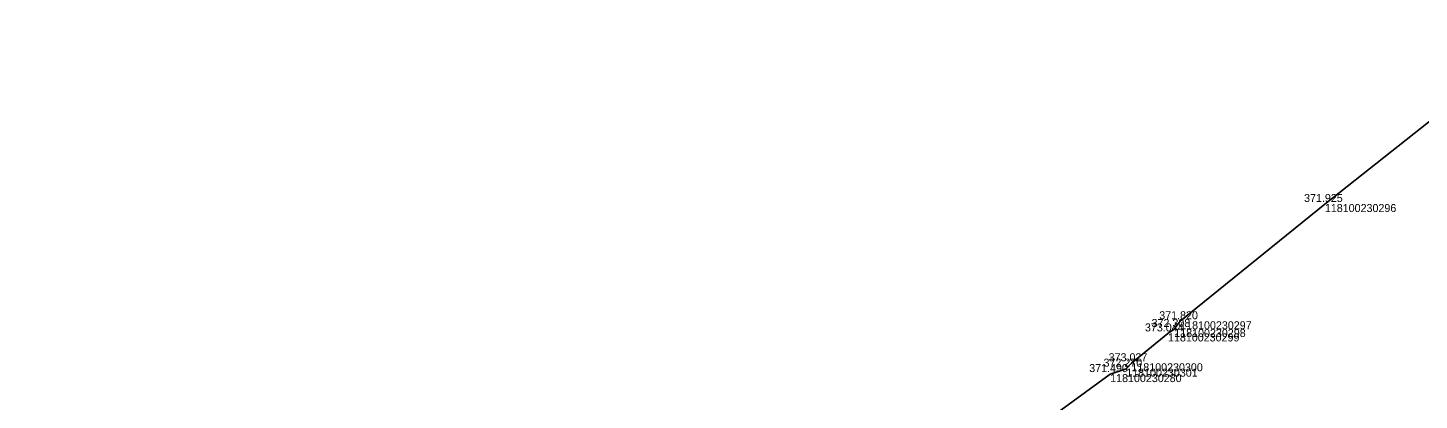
# Model space of a CAD drawing. Extents: x -732194 to -724760, y -944826 to -941477.
# Drawn here: x -731285.3 to -731076.7, y -942063.9 to -942008.1 of the extents above; entities that cross this region are included whole.
import ezdxf

# ---------------------------------------------------------------- set-up
doc = ezdxf.new("R2010")
doc.units = 0
for name, color, linetype in [('Vrstva 28', 7, 'Continuous'), ('Vrstva 31', 7, 'Continuous'), ('Vrstva 60', 7, 'Continuous'), ('Vrstva 61', 7, 'Continuous')]:
    doc.layers.add(name, color=color, linetype=linetype)

msp = doc.modelspace()

# ---------------------------------------------------------------- linework, layer by layer
at = {"layer": 'Vrstva 28'}
for points in [[(-731120.63, -942059.14), (-731119.86, -942058.33), (-731114.37, -942053.86), (-731113.43, -942053.2), (-731112.54, -942052.04), (-731090.85, -942034.48), (-731069.83, -942017.9), (-731057.45, -942008.09), (-731057.75, -942008.68)], [(-731285.31, -942325.58), (-731274.63, -942296.13), (-731267.63, -942279.07), (-731266.95, -942274.49), (-731266.31, -942268.77), (-731264.93, -942263.18), (-731264.13, -942256.92), (-731261.56, -942253.47), (-731256.01, -942237.5), (-731249.14, -942218.64), (-731239.5, -942196.85), (-731231.6, -942185.67), (-731225.39, -942175.28), (-731213.45, -942158.32), (-731200.78, -942140.85), (-731190.41, -942127.04), (-731184.79, -942121.18), (-731179.39, -942115.86), (-731166.81, -942100.28), (-731147.61, -942080.55), (-731141.71, -942075.09), (-731134.15, -942068.06), (-731123.04, -942059.95), (-731120.63, -942059.14)]]:
    msp.add_lwpolyline(points, dxfattribs=at)
at = {"layer": 'Vrstva 31'}
for points in [[(-731057.45, -942008.09), (-731069.83, -942017.9), (-731090.85, -942034.48), (-731112.54, -942052.04), (-731113.43, -942053.2), (-731114.37, -942053.86), (-731119.86, -942058.33), (-731120.63, -942059.14)], [(-731120.63, -942059.14), (-731123.04, -942059.95), (-731134.15, -942068.06)]]:
    msp.add_lwpolyline(points, dxfattribs=at)
at = {"layer": 'Vrstva 60'}
for p, q in [((-731090.85, -942034.48), (-731090.85, -942034.48)), ((-731113.43, -942053.2), (-731113.43, -942053.2)), ((-731112.54, -942052.04), (-731112.54, -942052.04)), ((-731114.37, -942053.86), (-731114.37, -942053.86)), ((-731123.04, -942059.95), (-731123.04, -942059.95)), ((-731120.63, -942059.14), (-731120.63, -942059.14)), ((-731119.86, -942058.33), (-731119.86, -942058.33))]:
    msp.add_line(p, q, dxfattribs=at)

# ---------------------------------------------------------------- texts
for s, p in [('118100230296', (-731090.85, -942035.68)), ('118100230298', (-731113.43, -942054.4)), ('118100230297', (-731112.54, -942053.24)), ('118100230299', (-731114.37, -942055.06)), ('118100230280', (-731123.04, -942061.15)), ('118100230301', (-731120.63, -942060.34)), ('118100230300', (-731119.86, -942059.53))]:
    msp.add_text(s, height=1.2, dxfattribs=at).set_placement(p)
at = {"layer": 'Vrstva 61'}
for s, p in [('371.925', (-731093.97, -942034.18)), ('371.820', (-731115.68, -942051.74)), ('373.044', (-731117.83, -942053.56)), ('372.308', (-731116.83, -942052.9)), ('372.270', (-731124.03, -942058.84)), ('373.027', (-731123.27, -942058.03)), ('371.490', (-731126.18, -942059.65))]:
    msp.add_text(s, height=1.2, dxfattribs=at).set_placement(p)

doc.saveas('drawing.dxf')
